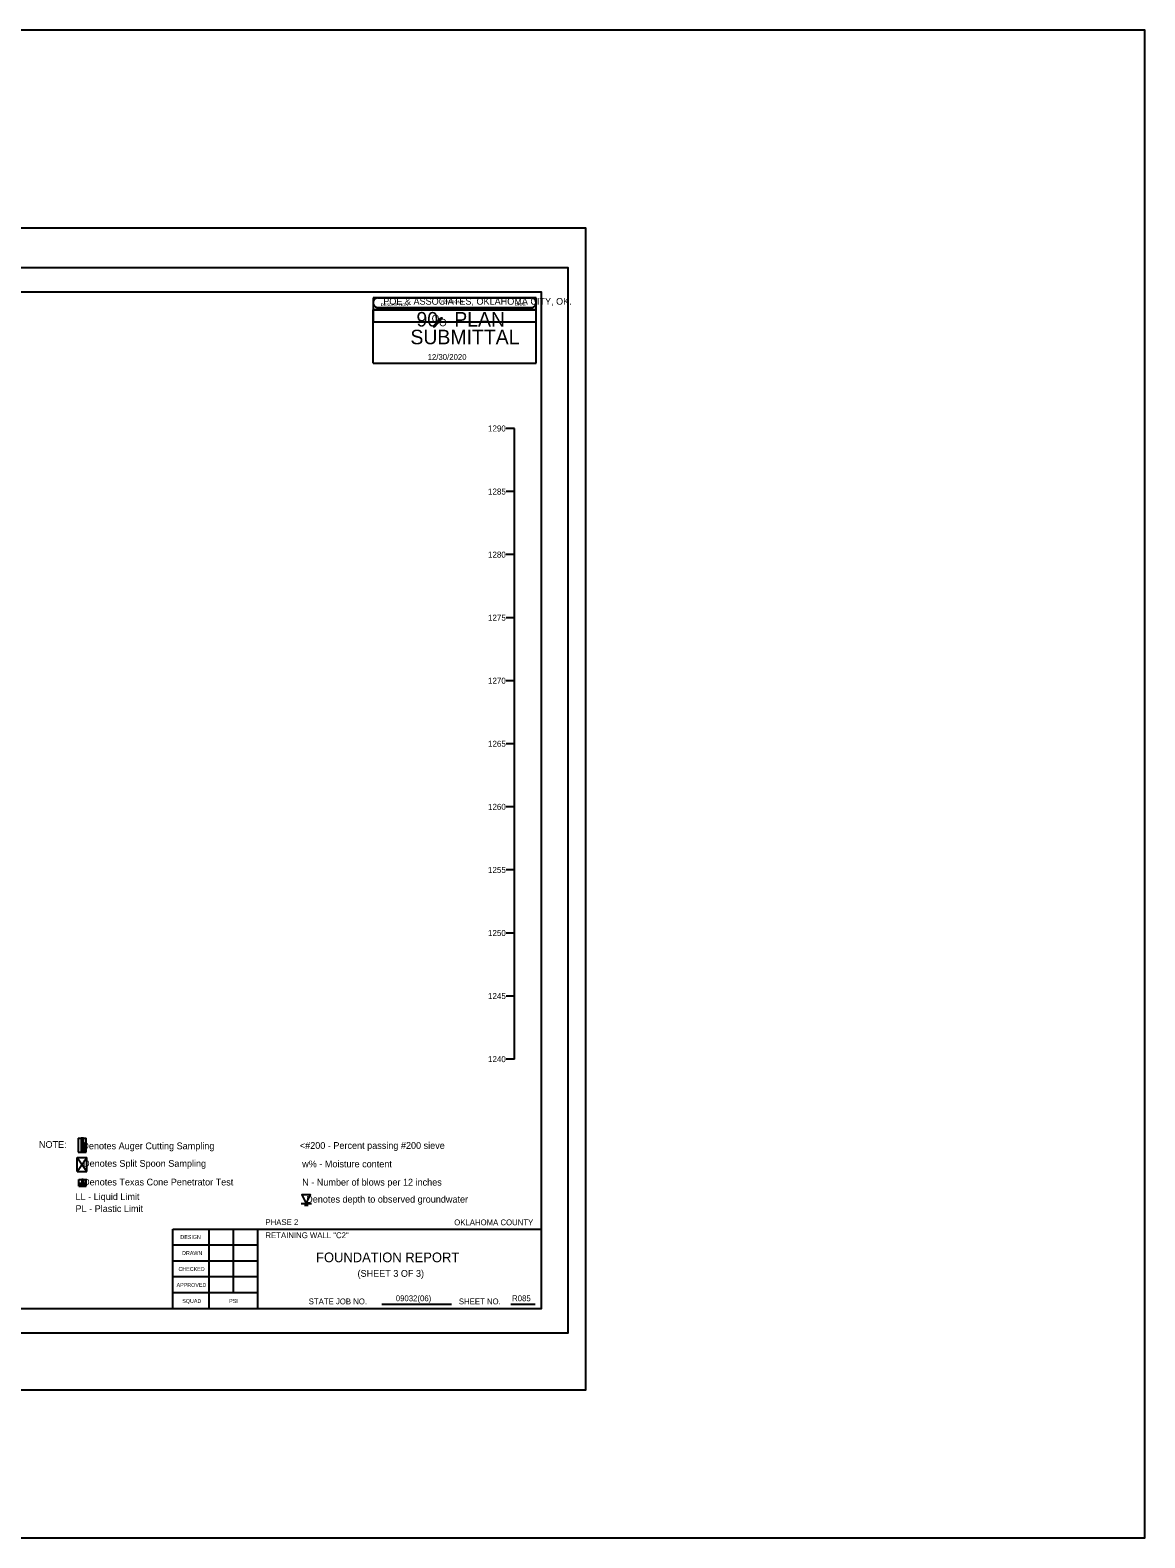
# Model space of a CAD drawing. Extents: x -2 to 138, y 24 to 58.
# Drawn here: x 114.52 to 137.53, y 26.92 to 58.05 of the extents above; entities that cross this region are included whole.
import ezdxf

# ---------------------------------------------------------------- set-up
doc = ezdxf.new("R2010")
doc.units = 0
for name, color, linetype in [('4', 7, 'Continuous'), ('S', 7, 'Continuous'), ('SHT_Plot_Shape_Full', 7, 'Continuous'), ('SHT_Plot_Shape_Half', 7, 'Continuous'), ('SHT_Sheet_Border', 7, 'Continuous'), ('SHT_Stamp_90_Submit', 7, 'Continuous'), ('SHT_Stamp_Rev_Block', 7, 'Continuous'), ('SHT_Standard_Sheet_Lines', 7, 'Continuous'), ('SHT_Standard_Sheet_Txt', 7, 'Continuous'), ('T', 7, 'Continuous'), ('T-5', 7, 'Continuous'), ('Text', 7, 'Continuous')]:
    doc.layers.add(name, color=color, linetype=linetype)

# ---------------------------------------------------------------- blocks, each defined once
blk = doc.blocks.new('DGRFC_WTLEV1_1')
for points in [[(-0.005, 0), (0.005, 0)], [(0, 0), (0.0042, 0.0083), (-0.0042, 0.0083), (0, 0)], [(-0.0017, -0.0017), (0.0017, -0.0017)]]:
    blk.add_lwpolyline(points)

msp = doc.modelspace()

# ---------------------------------------------------------------- linework, layer by layer
for p, q in [((124.513, 36.804), (124.513, 49.825)), ((115.51, 35.172), (115.51, 34.881))]:
    msp.add_line(p, q)
for points in [[(124.513, 49.825), (124.346, 49.825)], [(124.513, 48.523), (124.346, 48.523)], [(124.513, 47.221), (124.346, 47.221)], [(124.513, 45.919), (124.346, 45.919)], [(124.513, 44.617), (124.346, 44.617)], [(124.513, 43.315), (124.346, 43.315)], [(124.513, 42.013), (124.346, 42.013)], [(124.513, 40.711), (124.346, 40.711)], [(124.513, 39.408), (124.346, 39.408)], [(124.513, 38.106), (124.346, 38.106)], [(124.513, 36.804), (124.346, 36.804)], [(115.51, 35.172), (115.676, 35.172)], [(115.51, 34.881), (115.676, 34.881)], [(115.51, 34.881), (115.676, 34.881)], [(115.676, 34.881), (115.676, 35.172)]]:
    msp.add_lwpolyline(points)
for points in [[(115.568, 35.172), (115.568, 34.881), (115.618, 34.881), (115.618, 35.172)], [(115.633, 35.005), (115.627, 35.047), (115.618, 35.087), (115.633, 35.005)], [(115.618, 35.087), (115.618, 34.881), (115.633, 35.005), (115.618, 35.087)], [(115.618, 34.881), (115.633, 34.922), (115.633, 35.005), (115.618, 34.881)], [(115.618, 34.881), (115.627, 34.881), (115.633, 34.922), (115.618, 34.881)], [(115.633, 34.922), (115.635, 34.963), (115.633, 35.005), (115.633, 34.922)]]:
    msp.add_lwpolyline(points, close=True)
at = {"layer": 'S'}
msp.add_lwpolyline([(-2.212, 26.92), (137.529, 26.92), (137.529, 58.049), (-2.212, 58.049)], close=True, dxfattribs=at)
at = {"layer": 'SHT_Plot_Shape_Full'}
msp.add_lwpolyline([(89.979, 53.971), (125.979, 53.971), (125.979, 29.971), (89.979, 29.971)], close=True, dxfattribs=at)
at = {"layer": 'SHT_Plot_Shape_Half'}
msp.add_lwpolyline([(91.616, 53.146), (125.616, 53.146), (125.616, 31.146), (91.616, 31.146)], close=True, dxfattribs=at)
at = {"layer": 'SHT_Sheet_Border'}
for p, q in [((117.466, 31.646), (117.466, 33.296)), ((117.466, 33.296), (125.066, 33.296)), ((119.216, 31.646), (119.216, 33.297))]:
    msp.add_line(p, q, dxfattribs=at)
msp.add_lwpolyline([(93.566, 52.646), (125.066, 52.646), (125.066, 31.646), (93.566, 31.646)], close=True, dxfattribs=at)
at = {"layer": 'SHT_Stamp_90_Submit'}
for p, q in [((121.697, 52.522), (124.863, 52.522)), ((121.697, 52.322), (124.863, 52.322)), ((121.597, 52.272), (124.963, 52.272)), ((121.597, 51.173), (121.597, 52.272)), ((122.84, 51.934), (122.996, 52.107)), ((122.858, 51.934), (123.014, 52.107)), ((122.863, 51.934), (123.019, 52.107)), ((122.871, 51.934), (123.027, 52.107)), ((122.996, 52.107), (123.027, 52.107)), ((124.963, 51.173), (124.963, 52.272)), ((122.84, 51.934), (122.871, 51.934)), ((121.597, 51.173), (124.963, 51.173))]:
    msp.add_line(p, q, dxfattribs=at)
for centre, start, end in [((121.698, 52.422), 89.9952, 270), ((124.863, 52.422), 270, 90.0048)]:
    msp.add_arc(centre, 0.1, start, end, dxfattribs=at)
at = {"layer": 'SHT_Stamp_Rev_Block'}
for p, q in [((121.598, 52.522), (121.598, 52.022)), ((124.963, 52.522), (121.598, 52.522)), ((124.963, 52.022), (124.963, 52.522)), ((124.963, 52.272), (121.598, 52.272)), ((124.963, 52.022), (121.598, 52.022))]:
    msp.add_line(p, q, dxfattribs=at)
at = {"layer": 'SHT_Standard_Sheet_Lines'}
for p, q in [((118.216, 31.646), (118.216, 33.297)), ((118.716, 31.976), (118.716, 33.297)), ((121.777, 31.742), (123.217, 31.742)), ((124.442, 31.742), (124.944, 31.742))]:
    msp.add_line(p, q, dxfattribs=at)
for points in [[(119.216, 32.966), (117.466, 32.966)], [(119.216, 32.636), (117.466, 32.636)], [(119.216, 32.306), (117.466, 32.306)], [(119.216, 31.976), (117.466, 31.976)]]:
    msp.add_lwpolyline(points, dxfattribs=at)
at = {"layer": 'Text'}
for p, q in [((115.486, 34.481), (115.486, 34.773)), ((115.522, 34.181), (115.522, 34.322))]:
    msp.add_line(p, q, dxfattribs=at)
for points in [[(115.486, 34.481), (115.686, 34.773)], [(115.486, 34.773), (115.686, 34.481)], [(115.486, 34.773), (115.686, 34.773)], [(115.686, 34.481), (115.686, 34.773)], [(115.486, 34.481), (115.686, 34.481)], [(115.522, 34.322), (115.672, 34.322)], [(115.672, 34.181), (115.672, 34.322)], [(115.522, 34.181), (115.672, 34.181)]]:
    msp.add_lwpolyline(points, dxfattribs=at)
for points in [[(115.582, 34.237), (115.612, 34.322), (115.582, 34.322), (115.582, 34.237)], [(115.582, 34.237), (115.612, 34.237), (115.612, 34.322), (115.582, 34.237)], [(115.582, 34.237), (115.522, 34.237), (115.597, 34.181), (115.582, 34.237)], [(115.582, 34.237), (115.597, 34.181), (115.612, 34.237), (115.582, 34.237)], [(115.597, 34.181), (115.672, 34.237), (115.612, 34.237), (115.597, 34.181)]]:
    msp.add_lwpolyline(points, close=True, dxfattribs=at)

# ---------------------------------------------------------------- block references
at = {"layer": 'Text', "xscale": 21.6, "yscale": 21.6}
msp.add_blockref('DGRFC_WTLEV1_1', (120.217, 33.823), dxfattribs=at)

# ---------------------------------------------------------------- texts
for s, p in [('1290', (123.969, 49.763)), ('1285', (123.969, 48.461)), ('1280', (123.969, 47.159)), ('1275', (123.969, 45.857)), ('1270', (123.969, 44.555)), ('1265', (123.969, 43.253)), ('1260', (123.969, 41.951)), ('1255', (123.969, 40.649)), ('1250', (123.969, 39.346)), ('1245', (123.969, 38.044)), ('1240', (123.969, 36.742))]:
    msp.add_text(s, height=0.124).set_placement(p)
at = {"layer": '4'}
msp.add_text('FOUNDATION REPORT', height=0.2, dxfattribs=at).set_placement((120.42, 32.611))
at = {"layer": 'SHT_Stamp_90_Submit'}
for s, height, p in [('POE & ASSOCIATES, OKLAHOMA CITY, OK.', 0.14, (121.807, 52.38)), ('90   PLAN', 0.3, (122.492, 51.93)), ('O', 0.153, (122.806, 52.019)), ('O', 0.153, (122.958, 51.935)), ('SUBMITTAL', 0.3, (122.368, 51.564)), ('12/30/2020', 0.12, (122.723, 51.241))]:
    msp.add_text(s, height=height, dxfattribs=at).set_placement(p)
at = {"layer": 'SHT_Stamp_Rev_Block'}
for s, height, p in [('DESCRIPTION', 0.05999, (121.757, 52.351)), ('REVISIONS', 0.06, (123.006, 52.41)), ('DATE', 0.06, (124.527, 52.355))]:
    msp.add_text(s, height=height, dxfattribs=at).set_placement(p)
at = {"layer": 'SHT_Standard_Sheet_Txt'}
for s, height, p in [('DESIGN', 0.08, (117.619, 33.091)), ('DRAWN', 0.08, (117.654, 32.761)), ('CHECKED', 0.08, (117.58, 32.431)), ('APPROVED', 0.08, (117.541, 32.101)), ('SQUAD', 0.08, (117.658, 31.771)), ('PSI', 0.08, (118.625, 31.771)), ('STATE JOB NO.', 0.12, (120.268, 31.742)), ('SHEET NO. ', 0.12, (123.368, 31.742))]:
    msp.add_text(s, height=height, dxfattribs=at).set_placement(p)
at = {"layer": 'T'}
for s, p in [('PHASE 2', (119.375, 33.379)), ('OKLAHOMA COUNTY', (123.272, 33.374)), ('RETAINING WALL "C2" ', (119.375, 33.108)), ('09032(06)', (122.066, 31.806)), ('R085', (124.467, 31.806))]:
    msp.add_text(s, height=0.12, dxfattribs=at).set_placement(p)
at = {"layer": 'T-5'}
msp.add_text('(SHEET 3 OF 3)', height=0.14, dxfattribs=at).set_placement((121.276, 32.31))
at = {"layer": 'Text'}
for s, p in [('NOTE:', (114.699, 34.972)), ('    Denotes Auger Cutting Sampling', (115.387, 34.943)), (' <#200 - Percent passing #200 sieve', (120.033, 34.951)), ('    Denotes Split Spoon Sampling', (115.402, 34.581)), ('w% - Moisture content', (120.133, 34.57)), ('    Denotes Texas Cone Penetrator Test', (115.402, 34.196)), ('N - Number of blows per 12 inches', (120.133, 34.193)), (' LL - Liquid Limit', (115.402, 33.895)), ('    Denotes depth to observed groundwater', (120.009, 33.841)), (' PL - Plastic Limit', (115.402, 33.648))]:
    msp.add_text(s, height=0.14, dxfattribs=at).set_placement(p)

doc.saveas('drawing.dxf')
